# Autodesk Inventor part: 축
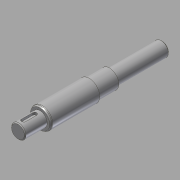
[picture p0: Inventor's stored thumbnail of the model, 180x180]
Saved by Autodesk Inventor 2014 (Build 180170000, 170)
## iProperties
Created: 2019-01
Part Number: 축
Material: 강철, 탄소
Document SubType Name: Modeling
Designer: mduedu
Density: 7.87 g/cm^3
Mass: 452.778 g
Surface Area: 120.904 cm^2
Volume: 57.5322 cm^3
Appearance: Steel
Author: mduedu
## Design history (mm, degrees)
sketch "스케치1"
  geometry: L1 (0, 0)-(26, 0); L2 (26, 0)-(26, 8.5); L3 (26, 8.5)-(0, 8.5); L4 (0, 8.5)-(0, 0); L5 (26, 0)-(84, 0); L6 (84, 0)-(84, 12.5); L7 (84, 12.5)-(26, 12.5); L8 (26, 12.5)-(26, 0); L9 (84, 0)-(108, 0); L10 (108, 0)-(108, 11); L11 (108, 11)-(84, 11); L12 (84, 11)-(84, 0); L13 (108, 0)-(170, 0); L14 (170, 0)-(170, 8.5); L15 (170, 8.5)-(108, 8.5); L16 (108, 8.5)-(108, 0)
  constraints: 32 end point, 8 parallel, 4 horizontal, 4 perpendicular
  dimensions: "d0" = 170 distance between parallel lines of L14 L4; "d2" = 26 distance of L2.end L3.end; "d3" = 24 distance of L10.end L11.end; "d4" = 62 distance of L14.end L15.end; "d5" = 17 diameter of L3 L1; "d6" = 25 diameter of L7 L5; "d7" = 22 diameter of L11 L9; "d8" = 17 diameter of L15 L13
revolve "회전1" sketch "스케치1" stored, may be unused: angle "d9" = 90 deg
node "작업 평면1"
sketch "스케치2" dims "d13" = 18
  geometry: L1 (6.5, -2.5)-(-6.5, -2.5); L2 (-6.5, -2.5)-(-6.5, 2.5); L3 (-6.5, 2.5)-(6.5, 2.5); L4 (6.5, 2.5)-(6.5, -2.5); L5 (13, 8.5)-(13, -8.5) reference; 3 further points
  constraints: 8 end point, 2 midpoint, 2 parallel, 2 vertical alignment, 1 horizontal, 1 horizontal alignment, 1 perpendicular, 4 other
  dimensions: "d10" = 5 distance between parallel lines of L3 L1; "d12" = 4 dimension on L5
extrude "돌출1" cut sketch "스케치2" distance "d14" = 3; taper "d15" = 0 deg
node "작업 평면2"
sketch "스케치3" dims "d19" = 18
  geometry: L1 (-24.5, -2.5)-(-11.5, -2.5); L2 (-11.5, -2.5)-(-11.5, 2.5); L3 (-11.5, 2.5)-(-24.5, 2.5); L4 (-24.5, 2.5)-(-24.5, -2.5); L5 (-31, 8.5)-(-31, -8.5) reference; 3 further points
  constraints: 8 end point, 2 midpoint, 2 parallel, 2 vertical alignment, 1 horizontal, 1 horizontal alignment, 1 perpendicular, 4 other
  dimensions: "d16" = 5 distance between parallel lines of L3 L1; "d18" = 4 dimension on L5
extrude "돌출2" cut sketch "스케치3" distance "d20" = 3; taper "d21" = 0 deg
chamfer "모따기1" distance "d22" = 1; stored, may be unused: second distance "d23" = 2, angle "d24" = 45 deg
chamfer "모따기2" distance "d25" = 2; stored, may be unused: second distance "d26" = 2, angle "d27" = 30 deg
fillet "모깎기2" dims "d30" = 2
node "솔리드1"
